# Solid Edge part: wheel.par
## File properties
Username: m_hel
Author: m_hel
Template: Iso Metric Part.par
Last saved by: m_hel
Revision: 10
Application: Solid Edge
Accuracy: 0,990
Material: Chrome
Face Style: Chrome
Fill Style: Normal
Virtual Style: Normal
Grouping: Uncategorized
LibraryName: Custom Materials
Coef. of Thermal Exp: 0.0
Thermal Conductivity: 0.0
Specific Heat: 0.0
Modulus of Elasticity: 0.0
Poisson's Ratio: 0.0
Yield Stress: 0.0
Ultimate Stress: 0.0
Elongation: 0.0
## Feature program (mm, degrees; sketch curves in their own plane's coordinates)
sketch for "unnamed RevolvedProtrusion 1" plane through (0, 0, 0) normal (0, -1, 0) x-axis (1, 0, 0)
  line (0, 63.4359) -> (0, 84.067)
  line (-175, 3.534) -> (-145.0808, 5.7345)
  line (-175, 0) -> (-175, 3.534)
  line (-175, 0) -> (-140, 0)
revolve "unnamed RevolvedProtrusion 1" add full turn 360 deg
sketch for "unnamed Cutout 1" plane through (-22.247, -63.5991, 0) normal (0, 0, 1) x-axis (-0.5, 0.866025, 0)
  line (87.9099, 0) -> (186.046, 51.0864)
  line (203.4671, 20.9122) -> (186.046, 51.0864)
  line (203.4671, 20.9122) -> (110.157, -38.533)
  arc centre (161.3038, -118.8174) radius 95.1924 from (110.157, -38.533) to (66.202, -114.6652) ccw
  line (66.202, -114.6652) -> (61.3761, -225.1968)
  line (26.5339, -225.1968) -> (61.3761, -225.1968)
  line (26.5339, -225.1968) -> (21.7079, -114.6652)
  arc centre (-73.3939, -118.8174) radius 95.1924 from (21.7079, -114.6652) to (-22.247, -38.533) ccw
  line (-22.247, -38.533) -> (-115.5572, 20.9122)
  line (-98.1361, 51.0864) -> (-115.5572, 20.9122)
  line (-98.1361, 51.0864) -> (0, 0)
  arc centre (43.955, 84.4367) radius 95.1924 from (0, 0) to (87.9099, 0) ccw
extrude "unnamed Cutout 1" cut through along +normal
sketch for "unnamed RevolvedProtrusion 2" plane through (0, 0, 0) normal (0, -1, 0) x-axis (1, 0, 0)
  circle centre (-175, 0) radius 15
revolve "unnamed RevolvedProtrusion 2" add finite 360 deg
fillet "Round_4" radius 2
sketch for "ExtrudedProtrusion_1" plane through (0, 0, 300) normal (0, 0, 1) x-axis (1, 0, 0)
extrude "ExtrudedProtrusion_1" add through along -normal  Profile_Plane1_Distance = 300 mm
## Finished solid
Body 1: solid body, 74 faces, 170 edges, 96 vertices.
  Faces by surface: blend 42, cylinder 10, plane 10, torus 7, cone 3, spun 2
  Edges by curve: intersection 84, circle 68, line 18
Bounding box of the edges (mm; curved faces can reach further): 295.894 x 258.360 x 301.765, from (-147.9471, -161.2099, -1.7647) to (147.9471, 97.1498, 300).
Cylindrical faces by radius (mm): R2 x6, R15 x1, R95.1924 x3
Conical faces (half-angle, radius in mm at the cone's reference point): 85.7936 deg R145.0808 x3
Toroidal faces (ring radius, tube radius in mm): R158.1181 r2 x3, R159.3712 r2 x3, R175 r15 x1
Planar faces by outward normal: +z 1, -z 3, oblique 6
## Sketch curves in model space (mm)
line (0, 0, 63.4359) -> (10.6911, 0, 63.4359)
line (0, 0, 84.067) -> (10.6911, 0, 84.067)
line (0, 0, 63.4359) -> (0, 0, 84.067)
line (0, 0, 28.2705) -> (0, 0, -28.4313)
spline (-140, 0, 0) -> (-81.63, 0, 31.7179) -> (0, 0, 63.4359)
spline (-145.0808, 0, 5.7345) -> (-82.4392, 0, 45.5761) -> (0, 0, 84.067)
line (-175, 0, 3.534) -> (-145.0808, 0, 5.7345)
line (-175, 0, 0) -> (-175, 0, 3.534)
line (-175, 0, 0) -> (-140, 0, 0)
circle centre (0, 0, 0) radius 175
line (0, 0, 0) -> (155.2269, 80.806, 0)
line (-155.2269, 80.806, 0) -> (0, 0, 0)
line (43.955, 51.0661, 0) -> (142.0911, 102.1525, 0)
arc centre (0, 135.5028, 0) radius 95.1924 from (-43.955, 51.0661, 0) through (0, 40.3103, 0) to (43.955, 51.0661, 0)
line (-142.0911, 102.1525, 0) -> (-43.955, 51.0661, 0)
line (0, 0, 28.2705) -> (0, 0, -28.4313)
circle centre (-175, 0, 0) radius 15
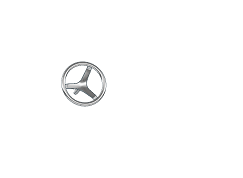
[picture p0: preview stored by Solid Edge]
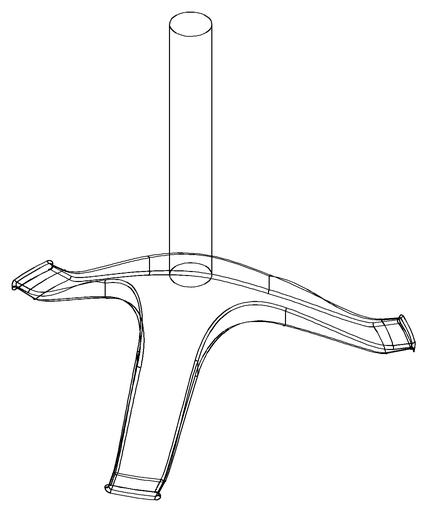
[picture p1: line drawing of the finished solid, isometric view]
